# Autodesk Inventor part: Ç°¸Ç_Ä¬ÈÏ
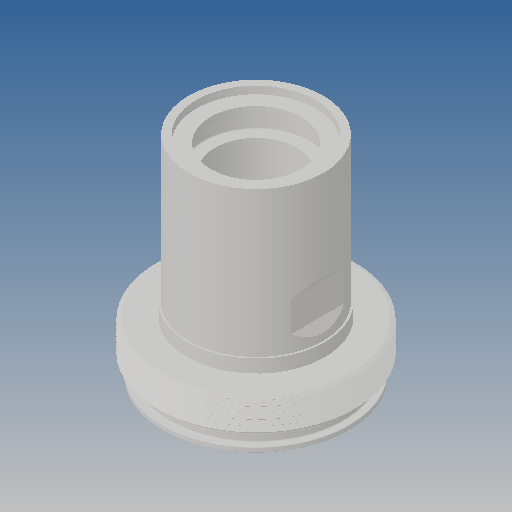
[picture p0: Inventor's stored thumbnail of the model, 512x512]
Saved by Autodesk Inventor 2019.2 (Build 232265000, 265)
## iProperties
Created: 2012-03
Part Number: Ç°¸Ç_Ä¬ÈÏ
Material: Ogólny
Document SubType Name: Modeling
Designer: CADENGINEERING4
Density: 1 g/cm^3
Appearance: Domyślna
Author: CADENGINEERING4
Revision Number: ÈÎºÎ
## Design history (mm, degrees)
feature "NONE"
node "Bryła1"
